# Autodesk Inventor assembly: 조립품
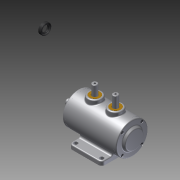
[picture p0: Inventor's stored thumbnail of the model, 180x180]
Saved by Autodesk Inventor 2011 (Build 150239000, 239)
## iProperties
Created: 2014-12
Part Number: 조립품
Document SubType Name: Assembly
Designer: user
Author: user
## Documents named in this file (10)
- D:\441225V1012\조립품.iam
- D:\441225V1012\본체.ipt
- D:\441225V1012\앞커버.ipt
- D:\441225V1012\오일실.ipt
- D:\441225V1012\축.ipt
- D:\441225V1012\M4-소켓머리.ipt
- D:\441225V1012\뒷커버.ipt
- D:\441225V1012\베어링 6203.ipt
- D:\441225V1012\부시.ipt
- D:\441225V1012\슬라이더.ipt
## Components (12 placed, 3 different names)
1. 8-오일실:2
2. 8-오일실:3
3. 7-베어링 6203:2
4. 7-베어링 6203:3
5. 9-M4-소켓머리:1
6. 9-M4-소켓머리:13
7. 9-M4-소켓머리:14
8. 9-M4-소켓머리:15
9. 9-M4-소켓머리:2
10. 9-M4-소켓머리:16
11. 9-M4-소켓머리:17
12. 9-M4-소켓머리:18
